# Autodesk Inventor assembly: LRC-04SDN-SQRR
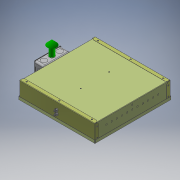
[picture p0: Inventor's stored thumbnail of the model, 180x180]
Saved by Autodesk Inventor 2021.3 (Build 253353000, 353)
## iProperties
load_classification: Lighting
motor: 0 ul
Part Number: LRC-04SDN-SQRR
Document SubType Name: Assembly
Designer: JChurch
Author: JChurch
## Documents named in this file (6)
- X:\Revit Files\0000-Un-Zipped\COB\LRC-04SDN-SQR\LRC-04SDN-SQRR.iam
- X:\INVENTOR\830\830557-00-00.iam
- X:\INVENTOR\885\885000-00-00.iam
- X:\INVENTOR\750\750206-00-00.iam
- X:\INVENTOR\725\725292-00-00.ipt
- X:\Revit Files\0000-Un-Zipped\COB\LRC-04SDN-SQR\LRC-04SDN-SQRR_Substitute_1.ipt
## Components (5 placed, 5 different names)
1. 830557-00-00:1 [sub-assembly] — Mate:1, Mate:2, Mate:3, Mate:4, Mate:5, Angle:1, Mate:9, Mate:10, Mate:11
2. 885000-00-00:1 [sub-assembly] — Mate:4, Mate:5, Angle:1
3. 750206-00-00:1 [sub-assembly] — Mate:6, Mate:7, Mate:8, Mate:9, Mate:10, Mate:11
4. 725292-00-00:1 — Mate:6, Mate:7, Mate:8
5. LRC-04SDN-SQRR_Substitute_1:1
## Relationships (12: Mate 11, Angle 1)
- Mate:1: 830557-00-00:1
- Mate:2: 830557-00-00:1
- Mate:3: 830557-00-00:1
- Mate:4: 830557-00-00:1 ↔ 885000-00-00:1
- Mate:5: 830557-00-00:1 ↔ 885000-00-00:1
- Angle:1: 830557-00-00:1 ↔ 885000-00-00:1
- Mate:6: 750206-00-00:1 ↔ 725292-00-00:1
- Mate:7: 750206-00-00:1 ↔ 725292-00-00:1
- Mate:8: 750206-00-00:1 ↔ 725292-00-00:1
- Mate:9: 830557-00-00:1 ↔ 750206-00-00:1
- Mate:10: 830557-00-00:1 ↔ 750206-00-00:1
- Mate:11: 830557-00-00:1 ↔ 750206-00-00:1
